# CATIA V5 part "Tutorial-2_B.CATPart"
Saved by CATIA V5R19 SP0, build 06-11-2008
Part number: Part1
Bounding box of the stored display mesh (mm): x 0 to 32, y -32 to 32, z -15 to 36
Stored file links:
  D:\Shriniwas\v5_r19\Part files\c07\c07tut2.CATPart
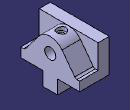
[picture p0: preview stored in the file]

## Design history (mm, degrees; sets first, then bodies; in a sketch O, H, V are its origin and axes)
Body1 (main body)
  Sketch1 on zx-plane, origin (0, 0, 0), H (-1, 0, 0), V (0, 0, 1)
    line L1 (0, 0) -> (0, 36)
    line L2 (0, 36) -> (-12, 36)
    line L3 (-12, 36) -> (-12, 10)
    line L4 (-12, 10) -> (-32, 10)
    line L5 (-32, 10) -> (-32, 0)
    point P5 (-32, 0)
    line L6 (-32, 0) -> (0, 0)
    length L1 = 36
    length L2 = 12
    length L5 = 10
    length L6 = 32
    vertical: L1 V, L3 V, L5 V
    horizontal: L2 H, L4 H, L6 H
    coincidence: P5 H
  Pad1: profile Sketch1, direction (0, 1, 0), length 32, mirrored extent
  Sketch2 on face of Pad1 from Sketch1.L5, origin (32, 0, 0), H (0, 1, 0), V (0, 0, 1)
    line L1 (0, 10) -> (27.5, 10)
    point P1 (0, 10)
    point P2 (27.5, 10)
    line L2 (27.5, 10) -> (12.8, 29.6)
    point P3 (12.8, 29.6)
    reference projected line E1 (-32, 10) -> (32, 10) from edge [face of Pad1 from Sketch1.L5 | face of Pad1 from Sketch1.L4]
    point P4 (-27.5, 10)
    point P5 (0, 10)
    line L3 (0, 10) -> (-27.5, 10)
    point P6 (-12.8, 29.6)
    line L4 (-27.5, 10) -> (-12.8, 29.6)
    arc A1 centre (0, 20) radius 16 from (12.8, 29.6) to (-12.8, 29.6) ccw
    reference projected line E2 (-32, 36) -> (32, 36) from edge [face of Pad1 from Sketch1.L3 | face of Pad1 from Sketch1.L2]
    radius A1 = 16
    distance P4 P2 = 55
    coincidence: P1 V, L1 E1, P1 P5
    horizontal: L1 H
    symmetry: P2 P4 V, P1 P5 V, L1 L3 V, P3 P6 V, L2 L4 V
    tangency: A1 L2, A1 E2
  Pad2: profile Sketch2, direction (1, 0, 0), up to the existing solid (limit type 2)
  Sketch3 on face of Pad2, origin (32, 0, 0), H (0, 1, 0), V (0, 0, 1)
    point P1 (-8, 0)
    line L1 (-8, 0) -> (8, 0)
    line L2 (8, 0) -> (8, -15)
    line L3 (8, -15) -> (-8, -15)
    line L4 (-8, -15) -> (-8, 0)
    length L3 = 16
    length L2 = 15
    distance L4 V = 8
    coincidence: P1 H
    horizontal: L1 H, L3 H
    vertical: L2 V, L4 V
  Pad3: profile Sketch3, direction (1, 0, 0), up to face of Pad1 from Sketch1.L1
  Sketch4 on zx-plane, origin (0, 0, 0), H (-1, 0, 0), V (0, 0, 1)
    point P1 (-20, 36)
    reference projected line E1 (0, 36) -> (-10, 36) from edge [face of Pad1 from Sketch1.L2 | end face of Pad1]
    distance P1 V = 20
    coincidence: P1 E1
  Sketch5 on {plane type Tangent, Support face of Pad2 from Sketch2.A1, RefPoint Sketch4.P1}, origin (20, 0, 36), H (1, 0, 0), V (0, -1, 0)
    point P1 (0, 0)
    reference projected point E1 (0, 0) from Sketch4.P1
    coincidence: E1 P1
  Hole1: placed by Sketch5, at (20, 0, 36) direction (0, 0, -1), diameter 6, depth 16, counterbore diameter 10, counterbore depth 4
  Fillet1: radius 3, on edge [face of Pad1 from Sketch1.L4 | face of Pad2 from Sketch2.L2]; edge [face of Pad2 from Sketch2.L4 | face of Pad1 from Sketch1.L4]
  Sketch6 on face of Pad3 from Sketch3.L3, origin (11.5351, 1.2048, -15), H (1, 0, 0), V (0, -1, 0)
    point P1 (-3.5351, 1.2048)
    reference projected line E1 (-11.5351, -6.7952) -> (-11.5351, 9.2048) from edge [face of Pad3 from Sketch3.L3 | end face of Pad3]
    reference projected line E2 (20.4649, -6.7952) -> (-11.5351, -6.7952) from edge [face of Pad3 from Sketch3.L3 | face of Pad3 from Sketch3.L2]
    distance P1 E1 = 8
    distance E2 P1 = 8
  Hole2: placed by Sketch6, at (8, 0, -15) direction (0, 0, 1), diameter 6, depth 16, V-bottom angle 120
  Sketch7 on face of Pad3 from Sketch3.L3, origin (26.6528, -0.5857, -15), H (1, 0, 0), V (0, -1, 0)
    point P1 (-2.6528, 0)
    reference projected line E1 (5.3472, -8.5857) -> (-26.6528, -8.5857) from edge [face of Pad3 from Sketch3.L3 | face of Pad3 from Sketch3.L2]
    reference projected point E2 (-18.6528, -0.5857) from edge
    distance E1 H = 8
    distance E2 P1 H = 16
  Hole3: placed by Sketch7, at (24, -0.5857, -15) direction (0, 0, 1), diameter 6, depth 16, V-bottom angle 120
  Sketch8 on face of Pad2, origin (32, -6.1541, 20.7645), H (0, 1, 0), V (0, 0, 1)
    point P1 (6.1541, -0.7645)
    reference projected arc E1 centre (6.1541, -0.7645) radius 16 from (18.9541, 8.8355) to (-6.6459, 8.8355) ccw from edge [face of Pad2 from Sketch2.A1 | start face of Pad2]
    concentricity: P1 E1
  Hole4: placed by Sketch8, at (32, 0, 20) direction (-1, 0, 0), diameter 12, depth 24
